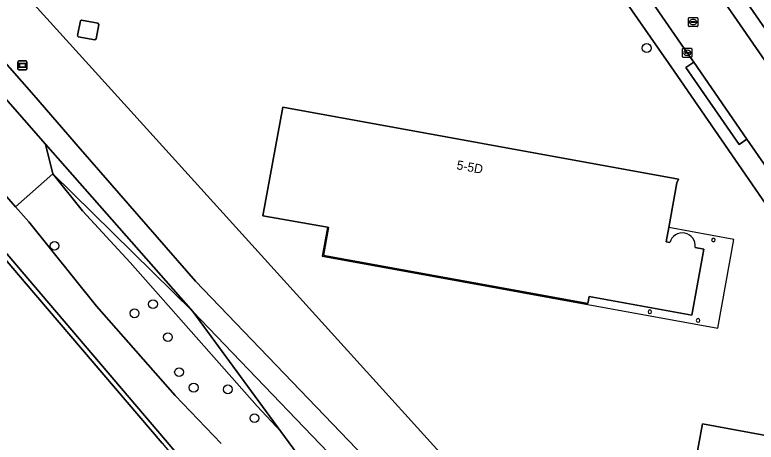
# Model space of a CAD drawing. Extents: x 157445 to 158888, y 383061 to 384688.
# Drawn here: x 157837.3 to 157918.7, y 383307.4 to 383354.3 of the extents above; entities that cross this region are included whole.
import ezdxf

# ---------------------------------------------------------------- set-up
doc = ezdxf.new("R2010")
doc.units = 0
for name, color, linetype in [('IMGEO_Boom', 7, 'Continuous'), ('IMGEO_Erf', 7, 'Continuous'), ('IMGEO_Groenvoorziening', 7, 'Continuous'), ('IMGEO_Hek', 7, 'Continuous'), ('IMGEO_Kademuur', 7, 'Continuous'), ('IMGEO_Kolk', 7, 'Continuous'), ('IMGEO_Lage_trafo', 7, 'Continuous'), ('IMGEO_Pand', 7, 'Continuous'), ('IMGEO_Pand_nummerreeks', 7, 'Continuous'), ('IMGEO_Pand_overbouw', 7, 'Continuous'), ('IMGEO_Parkeervlak_open', 7, 'Continuous'), ('IMGEO_Rijbaan_lokaal_open', 7, 'Continuous'), ('IMGEO_Rioolput', 7, 'Continuous'), ('IMGEO_Verklikker', 7, 'Continuous'), ('IMGEO_Voetpad_open', 7, 'Continuous'), ('IMGEO_Waterloop', 7, 'Continuous')]:
    doc.layers.add(name, color=color, linetype=linetype)

msp = doc.modelspace()

# ---------------------------------------------------------------- linework, layer by layer
at = {"layer": 'IMGEO_Boom'}
for centre in [(157906.68, 383350.678), (157841.696, 383328.967), (157852.507, 383322.562), (157850.476, 383321.561), (157854.135, 383318.939), (157855.368, 383315.097), (157856.961, 383313.396), (157860.715, 383313.208), (157863.638, 383310.047)]:
    msp.add_circle(centre, 0.489, dxfattribs=at)
at = {"layer": 'IMGEO_Erf'}
for points in [[(157976.607, 383304.584), (157965.542, 383320.73), (157957.186, 383314.977), (157955.59, 383314.069), (157951.478, 383311.189), (157932.838, 383314.613), (157928.425, 383320.955), (157925.669, 383324.951), (157909.683, 383348.132), (157898.462, 383364.319), (157895.075, 383369.235), (157890.311, 383376.164), (157886.385, 383381.901), (157886.267, 383381.935), (157881.344, 383389.058), (157877.36, 383394.852), (157877.384, 383395.064), (157877.163, 383395.127), (157872.582, 383395.96), (157873.507, 383400.495), (157873.121, 383401.062), (157849.565, 383405.324)], [(157807.532, 383390.715), (157849.702, 383344.141), (157889.589, 383300.088)], [(157912.951, 383328.611), (157911.634, 383321.36), (157900.354, 383323.422), (157900.211, 383322.635), (157871.213, 383327.905), (157871.774, 383330.989), (157871.636, 383331.013), (157864.564, 383332.268), (157866.745, 383344.174), (157910.161, 383336.285), (157909.984, 383335.877), (157909.096, 383330.992), (157908.806, 383329.395), (157909.219, 383329.321)], [(157911.997, 383328.784), (157912.951, 383328.611)]]:
    msp.add_lwpolyline(points, dxfattribs=at)
for points in [[(157846.262, 383351.692), (157846.113, 383351.597), (157844.307, 383351.917), (157844.217, 383352.067), (157844.534, 383353.659), (157844.666, 383353.744), (157846.434, 383353.431), (157846.561, 383353.282)], [(157973.956, 383287.176), (157968.185, 383255.919), (157940.482, 383261.02), (157941.47, 383266.327), (157921.996, 383269.931), (157924.28, 383282.398), (157920.851, 383283.039), (157921.496, 383286.457), (157909.007, 383288.798), (157912.788, 383309.42), (157933.424, 383305.609), (157931.787, 383296.632), (157931.406, 383294.544), (157933.186, 383294.192), (157935.682, 383290.562), (157935.356, 383288.832), (157937.476, 383288.439), (157945.227, 383287.003), (157946.228, 383292.288)]]:
    msp.add_lwpolyline(points, close=True, dxfattribs=at)
for centre, radius, start, end in [((157910.591, 383328.964), 1.418, 352.6968, 165.42201), ((157913.993, 383329.608), 0.2, 0, 180), ((157913.993, 383329.608), 0.2, 180, 0), ((157907.019, 383321.725), 0.2, 0, 180), ((157907.019, 383321.725), 0.2, 180, 360), ((157912.321, 383320.781), 0.2, 0, 180), ((157912.321, 383320.781), 0.2, 180, 0)]:
    msp.add_arc(centre, radius, start, end, dxfattribs=at)
at = {"layer": 'IMGEO_Groenvoorziening'}
for points in [[(157922.54, 383262.113), (157933.282, 383250), (157948.97, 383232.31), (157949.885, 383232.91), (157889.589, 383300.088), (157849.702, 383344.141), (157807.532, 383390.715), (157805.588, 383392.998), (157803.74, 383395.36), (157793.514, 383406.385), (157792.453, 383406.432), (157792.436, 383405.693), (157792.897, 383398.29), (157821.749, 383365.653), (157839.418, 383345.491), (157844.559, 383339.577), (157857.156, 383325.085), (157878.365, 383302.971), (157892.353, 383290.294), (157895.75, 383287.54), (157912.574, 383272.677)], [(157841.52, 383336.879), (157856.871, 383321.74), (157840.702, 383340.129)], [(157856.871, 383321.74), (157841.52, 383336.879), (157844.77, 383332.795), (157849.981, 383327.129), (157863.939, 383311.349), (157866.539, 383308.593)]]:
    msp.add_lwpolyline(points, close=True, dxfattribs=at)
for points in [[(157819.868, 383363.95), (157840.702, 383340.129), (157856.871, 383321.74), (157876.952, 383300.826), (157877.178, 383300.624), (157883.671, 383294.861), (157904.085, 383277.064), (157905.243, 383276.051), (157913.495, 383268.061), (157920.644, 383260.408), (157929.936, 383250), (157945.627, 383232.424), (157943.413, 383231.061), (157948.97, 383232.31), (157933.282, 383250), (157922.54, 383262.113), (157912.574, 383272.677), (157895.75, 383287.54), (157892.353, 383290.294), (157878.365, 383302.971), (157857.156, 383325.085), (157844.559, 383339.577), (157839.418, 383345.491), (157821.749, 383365.653)], [(157828.189, 383343.803), (157837.43, 383333.25), (157841.52, 383336.879), (157840.702, 383340.129), (157819.868, 383363.95)], [(157859.97, 383307.251), (157854.953, 383312.545), (157846.321, 383322.336), (157838.876, 383331.598), (157837.43, 383333.25), (157828.189, 383343.803)], [(157869.685, 383304.315), (157866.539, 383308.593), (157863.939, 383311.349), (157849.981, 383327.129), (157844.77, 383332.795), (157841.52, 383336.879), (157837.43, 383333.25), (157838.876, 383331.598), (157846.321, 383322.336), (157854.953, 383312.545), (157859.97, 383307.251)], [(157833.781, 383331.188), (157838.763, 383325.368), (157853.875, 383307.642), (157866.583, 383292.617)], [(157880.943, 383294.572), (157879.22, 383297.075), (157877.178, 383300.624), (157876.952, 383300.826), (157856.871, 383321.74), (157866.539, 383308.593), (157869.685, 383304.315), (157885.528, 383284.108), (157912.27, 383250), (157922.645, 383237.116), (157934.23, 383222.168), (157951.825, 383203.476), (157953.334, 383204.497)]]:
    msp.add_lwpolyline(points, dxfattribs=at)
at = {"layer": 'IMGEO_Hek'}
for points in [[(157849.702, 383344.141), (157807.532, 383390.715), (157805.588, 383392.998), (157803.74, 383395.36), (157793.514, 383406.385)], [(157889.589, 383300.088), (157849.702, 383344.141)]]:
    msp.add_lwpolyline(points, dxfattribs=at)
at = {"layer": 'IMGEO_Kademuur'}
msp.add_lwpolyline([(157833.403, 383330.862), (157838.382, 383325.044), (157853.494, 383307.318), (157866.203, 383292.293), (157876.661, 383280.152), (157887.441, 383267.609), (157896.454, 383257.066), (157899.566, 383253.379), (157914.743, 383236.05), (157915.119, 383236.379), (157914.241, 383237.382), (157912.362, 383239.528), (157899.945, 383253.705), (157896.835, 383257.389), (157887.821, 383267.935), (157877.04, 383280.478), (157866.583, 383292.617), (157853.875, 383307.642), (157838.763, 383325.368), (157833.781, 383331.188)], dxfattribs=at)
at = {"layer": 'IMGEO_Kolk'}
for p, q in [((157910.62, 383349.728), (157910.62, 383350.58)), ((157910.695, 383350.654), (157911.547, 383350.654)), ((157910.879, 383350.148), (157910.879, 383350.16)), ((157911.317, 383350.111), (157910.919, 383350.111)), ((157910.922, 383350.197), (157911.32, 383350.197)), ((157911.108, 383350.434), (157911.133, 383350.434)), ((157911.363, 383350.16), (157911.363, 383350.148)), ((157911.621, 383350.58), (157911.621, 383349.728)), ((157911.547, 383349.654), (157910.695, 383349.654)), ((157911.131, 383349.874), (157911.106, 383349.874))]:
    msp.add_line(p, q, dxfattribs=at)
for points in [[(157910.62, 383349.728), (157910.62, 383350.58)], [(157910.695, 383350.654), (157911.547, 383350.654)], [(157911.621, 383350.58), (157911.621, 383349.728)], [(157911.547, 383349.654), (157910.695, 383349.654)]]:
    msp.add_lwpolyline(points, dxfattribs=at)
for centre, radius, start, end in [((157910.697, 383350.578), 0.0765, 91.55205, 178.44795), ((157910.697, 383350.578), 0.0765, 91.55205, 178.44795), ((157910.919, 383350.157), 0.0403, 85.87752, 175.75265), ((157910.916, 383350.147), 0.0366, 178.93798, 274.71019), ((157911.32, 383350.154), 0.043, 264.86636, 352.45326), ((157911.324, 383350.159), 0.0386, 1.73085, 96.63898), ((157911.545, 383350.578), 0.0765, 1.55205, 88.44795), ((157911.545, 383350.578), 0.0765, 1.55205, 88.44795), ((157910.697, 383349.73), 0.0765, 181.55205, 268.44795), ((157910.697, 383349.73), 0.0765, 181.55205, 268.44795), ((157911.545, 383349.73), 0.0765, 271.55205, 358.44795), ((157911.545, 383349.73), 0.0765, 271.55205, 358.44795)]:
    msp.add_arc(centre, radius, start, end, dxfattribs=at)
for centre, major_axis, ratio, start_param, end_param in [((157911.107, 383350.154), (-0.387, 0.002), 0.722429, 4.712389, 7.853982), ((157911.132, 383350.154), (-0.39, 0.002), 0.717154, 1.570796, 4.712389)]:
    msp.add_ellipse(centre, major_axis=major_axis, ratio=ratio, start_param=start_param, end_param=end_param, dxfattribs=at)
at = {"layer": 'IMGEO_Lage_trafo'}
msp.add_lwpolyline([(157846.113, 383351.597), (157846.262, 383351.692), (157846.561, 383353.282), (157846.434, 383353.431), (157844.666, 383353.744), (157844.534, 383353.659), (157844.217, 383352.067), (157844.307, 383351.917)], close=True, dxfattribs=at)
at = {"layer": 'IMGEO_Pand'}
msp.add_lwpolyline([(157909.219, 383329.321), (157908.806, 383329.395), (157909.096, 383330.992), (157909.984, 383335.877), (157910.161, 383336.285), (157866.745, 383344.174), (157864.564, 383332.268), (157871.636, 383331.013), (157871.774, 383330.989), (157871.213, 383327.905), (157900.211, 383322.635), (157900.354, 383323.422), (157911.634, 383321.36), (157912.951, 383328.611), (157911.997, 383328.784)], dxfattribs=at)
msp.add_lwpolyline([(157937.476, 383288.439), (157935.356, 383288.832), (157935.682, 383290.562), (157933.186, 383294.192), (157931.406, 383294.544), (157931.787, 383296.632), (157933.424, 383305.609), (157912.788, 383309.42), (157909.007, 383288.798), (157921.496, 383286.457), (157920.851, 383283.039), (157924.28, 383282.398), (157921.996, 383269.931), (157941.47, 383266.327), (157940.482, 383261.02), (157968.185, 383255.919), (157973.956, 383287.176), (157946.228, 383292.288), (157945.227, 383287.003)], close=True, dxfattribs=at)
for centre, radius, start, end in [((157910.591, 383328.964), 1.418, 352.6968, 165.42201), ((157913.993, 383329.608), 0.2, 0, 180), ((157913.993, 383329.608), 0.2, 180, 0), ((157907.019, 383321.725), 0.2, 0, 180), ((157907.019, 383321.725), 0.2, 180, 360), ((157912.321, 383320.781), 0.2, 0, 180), ((157912.321, 383320.781), 0.2, 180, 0)]:
    msp.add_arc(centre, radius, start, end, dxfattribs=at)
at = {"layer": 'IMGEO_Pand_overbouw'}
for points in [[(157911.997, 383328.784), (157912.951, 383328.611), (157911.634, 383321.36), (157900.354, 383323.422), (157900.211, 383322.635), (157871.213, 383327.905), (157871.774, 383330.989), (157871.636, 383331.013), (157871.064, 383327.83), (157914.492, 383319.917), (157916.251, 383329.679), (157909.096, 383330.992)], [(157909.096, 383330.992), (157908.806, 383329.395), (157909.219, 383329.321)]]:
    msp.add_lwpolyline(points, dxfattribs=at)
msp.add_arc((157910.591, 383328.964), 1.418, 352.6968, 165.42201, dxfattribs=at)
at = {"layer": 'IMGEO_Parkeervlak_open'}
for points in [[(157863.215, 383431.182), (157863.862, 383430.224), (157871.979, 383418.406), (157880.805, 383405.562), (157894.321, 383385.972), (157905.565, 383369.639), (157915.623, 383355.122), (157935.388, 383326.53), (157935.643, 383326.174), (157936.465, 383325.145)], [(157936.153, 383328.952), (157907.044, 383371.058), (157890.489, 383394.989), (157884.813, 383403.235), (157866.622, 383429.736)]]:
    msp.add_lwpolyline(points, dxfattribs=at)
at = {"layer": 'IMGEO_Rijbaan_lokaal_open'}
msp.add_lwpolyline([(157876.859, 383399.812), (157883.617, 383389.989), (157889.899, 383380.858), (157890.097, 383380.63), (157892.494, 383377.128), (157897.603, 383369.765), (157899.471, 383367.034), (157900.174, 383366.038), (157907.035, 383356.127), (157911.123, 383350.155), (157911.832, 383349.127), (157917.679, 383340.677), (157921.646, 383334.932), (157926.89, 383327.295), (157930.145, 383322.573), (157930.847, 383321.656), (157936.465, 383325.145), (157935.643, 383326.174), (157935.388, 383326.53), (157915.623, 383355.122), (157905.565, 383369.639), (157894.321, 383385.972), (157880.805, 383405.562)], dxfattribs=at)
at = {"layer": 'IMGEO_Rioolput'}
for p, q in [((157911.345, 383354.04), (157912.197, 383354.04)), ((157911.27, 383353.114), (157911.27, 383353.966)), ((157911.529, 383353.534), (157911.529, 383353.546)), ((157911.967, 383353.497), (157911.569, 383353.497)), ((157911.572, 383353.583), (157911.97, 383353.583)), ((157911.781, 383353.26), (157911.756, 383353.26)), ((157911.758, 383353.82), (157911.783, 383353.82)), ((157912.013, 383353.546), (157912.013, 383353.534)), ((157912.271, 383353.966), (157912.271, 383353.114)), ((157912.197, 383353.04), (157911.345, 383353.04))]:
    msp.add_line(p, q, dxfattribs=at)
for points in [[(157911.345, 383354.04), (157912.197, 383354.04)], [(157911.27, 383353.114), (157911.27, 383353.966)], [(157912.271, 383353.966), (157912.271, 383353.114)], [(157912.197, 383353.04), (157911.345, 383353.04)]]:
    msp.add_lwpolyline(points, dxfattribs=at)
for centre, radius, start, end in [((157911.347, 383353.964), 0.0765, 91.55205, 178.44795), ((157911.347, 383353.964), 0.0765, 91.55205, 178.44795), ((157912.195, 383353.964), 0.0765, 1.55205, 88.44795), ((157912.195, 383353.964), 0.0765, 1.55205, 88.44795), ((157911.569, 383353.543), 0.0403, 85.87752, 175.75265), ((157911.566, 383353.533), 0.0366, 178.93798, 274.71019), ((157911.97, 383353.54), 0.043, 264.86636, 352.45326), ((157911.974, 383353.545), 0.0386, 1.73085, 96.63898), ((157911.347, 383353.116), 0.0765, 181.55205, 268.44795), ((157911.347, 383353.116), 0.0765, 181.55205, 268.44795), ((157912.195, 383353.116), 0.0765, 271.55205, 358.44795), ((157912.195, 383353.116), 0.0765, 271.55205, 358.44795)]:
    msp.add_arc(centre, radius, start, end, dxfattribs=at)
for centre, major_axis, ratio, start_param, end_param in [((157911.757, 383353.54), (-0.387, 0.002), 0.722429, 4.712389, 7.853982), ((157911.782, 383353.54), (-0.39, 0.002), 0.717154, 1.570796, 4.712389)]:
    msp.add_ellipse(centre, major_axis=major_axis, ratio=ratio, start_param=start_param, end_param=end_param, dxfattribs=at)
at = {"layer": 'IMGEO_Verklikker'}
for p, q in [((157837.678, 383348.38), (157837.678, 383349.18)), ((157837.678, 383349.18), (157837.678, 383348.38)), ((157837.778, 383349.28), (157838.568, 383349.28)), ((157838.568, 383349.28), (157837.778, 383349.28)), ((157838.668, 383349.18), (157838.668, 383348.38)), ((157838.668, 383348.38), (157838.668, 383349.18)), ((157838.568, 383348.28), (157837.778, 383348.28)), ((157837.778, 383348.28), (157838.568, 383348.28))]:
    msp.add_line(p, q, dxfattribs=at)
for points in [[(157837.779, 383349.012), (157838.567, 383349.012), (157838.567, 383348.548), (157837.779, 383348.548), (157837.779, 383349.012)], [(157837.844, 383348.947), (157837.844, 383348.613), (157838.502, 383348.613), (157838.502, 383348.947), (157837.844, 383348.947)]]:
    msp.add_lwpolyline(points, dxfattribs=at)
for centre, start, end in [((157837.778, 383349.18), 90, 180), ((157837.778, 383349.18), 90, 180), ((157838.568, 383349.18), 0, 90), ((157838.568, 383349.18), 360, 90), ((157837.778, 383348.38), 180, 270), ((157837.778, 383348.38), 180, 270), ((157838.568, 383348.38), 270, 0), ((157838.568, 383348.38), 270, 0)]:
    msp.add_arc(centre, 0.1, start, end, dxfattribs=at)
at = {"layer": 'IMGEO_Voetpad_open'}
for points in [[(157866.622, 383429.736), (157884.813, 383403.235), (157885.67, 383403.825), (157891.346, 383395.579), (157890.489, 383394.989), (157907.044, 383371.058), (157936.153, 383328.952)], [(157870.408, 383403.99), (157866.235, 383404.72), (157850.004, 383407.722), (157849.565, 383405.324), (157873.121, 383401.062), (157873.507, 383400.495), (157877.163, 383395.127), (157877.384, 383395.064), (157877.36, 383394.852), (157881.344, 383389.058), (157886.267, 383381.935), (157886.385, 383381.901), (157890.311, 383376.164), (157895.075, 383369.235), (157898.462, 383364.319), (157909.683, 383348.132), (157925.669, 383324.951)], [(157921.646, 383334.932), (157917.679, 383340.677), (157916.824, 383340.085), (157910.977, 383348.535), (157911.832, 383349.127), (157911.123, 383350.155), (157907.035, 383356.127), (157906.18, 383355.535), (157899.319, 383365.446), (157900.174, 383366.038), (157899.471, 383367.034), (157897.603, 383369.765), (157896.749, 383369.172), (157891.64, 383376.535), (157892.494, 383377.128), (157890.097, 383380.63), (157889.899, 383380.858), (157889.042, 383380.269), (157882.76, 383389.4), (157883.617, 383389.989), (157876.859, 383399.812)]]:
    msp.add_lwpolyline(points, dxfattribs=at)
msp.add_lwpolyline([(157917.679, 383340.677), (157911.832, 383349.127), (157910.977, 383348.535), (157916.824, 383340.085)], close=True, dxfattribs=at)
at = {"layer": 'IMGEO_Waterloop'}
msp.add_lwpolyline([(157853.494, 383307.318), (157838.382, 383325.044), (157833.403, 383330.862)], dxfattribs=at)

# ---------------------------------------------------------------- texts
at = {"layer": 'IMGEO_Pand_nummerreeks'}
msp.add_text('5-5D', height=1, rotation=349.70131, dxfattribs=at).set_placement((157885.759, 383337.385))

doc.saveas('drawing.dxf')
